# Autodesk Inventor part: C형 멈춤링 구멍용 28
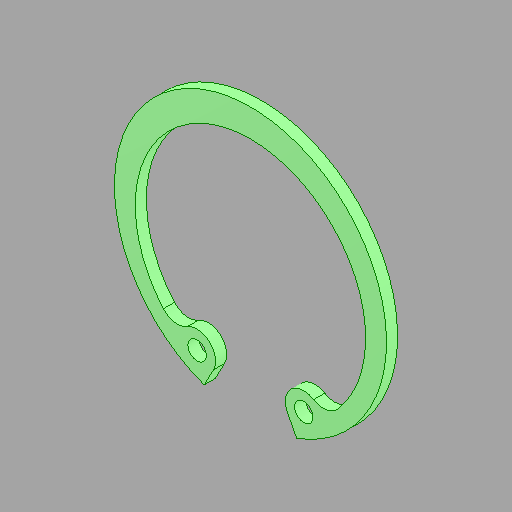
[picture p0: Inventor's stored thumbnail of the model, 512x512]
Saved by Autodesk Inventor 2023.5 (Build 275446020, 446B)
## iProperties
Created: 2026-03
Part Number: C형 멈춤링 구멍용 28
Material: 강철, 연강
Description: 리테이닝 링(C형)
Document SubType Name: Modeling
Designer: mirae
Density: 7.85 g/cm^3
Appearance: 기본값
Author: jhkim
Sending System: Autodesk Inventor 2026
Preprocessor: ST-DEVELOPER v20.1
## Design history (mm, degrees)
node "C형 멈춤링 구멍용 281"
node "솔리드1"
body "Solid1"
